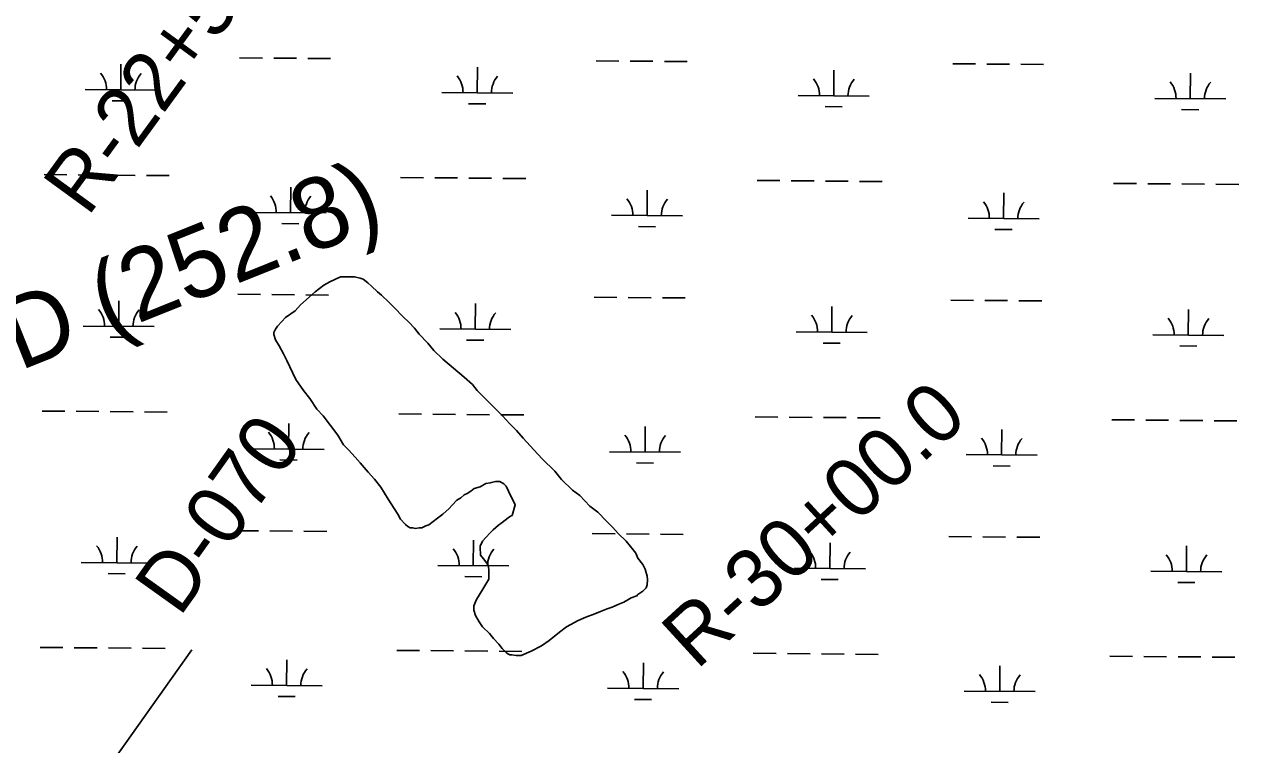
# Model space of a CAD drawing. Extents: x 3271442 to 3309282, y 752266 to 777610.
# Drawn here: x 3294405 to 3296115, y 767477 to 768491 of the extents above; entities that cross this region are included whole.
import ezdxf

# ---------------------------------------------------------------- set-up
doc = ezdxf.new("R2010")
doc.units = 0
for name, color, linetype in [('V-CHAN-NAID', 7, 'Continuous'), ('V-RIVR-RANG', 7, 'Continuous'), ('V-RIVR-RANG-IDEN', 7, 'Continuous'), ('V-SITE-VEGE', 7, 'Continuous'), ('V-WETL-SWMP', 7, 'Continuous')]:
    doc.layers.add(name, color=color, linetype=linetype)

msp = doc.modelspace()

# ---------------------------------------------------------------- linework, layer by layer
at = {"layer": 'V-RIVR-RANG'}
msp.add_line((3294641.4, 767611), (3293947, 766632.3), dxfattribs=at)
at = {"layer": 'V-SITE-VEGE'}
for points in [[(3294870.2, 768135.7), (3294850.4, 768135.7), (3294835.4, 768128.9), (3294827.3, 768124.2), (3294815, 768114.7), (3294794.5, 768096.3), (3294787, 768088.1), (3294773.4, 768078.6), (3294767.9, 768073.1), (3294761.8, 768066.3), (3294759, 768062.2), (3294757, 768057.5), (3294757, 768054.7), (3294759, 768047.2), (3294764.4, 768038.4), (3294770.6, 768027.4), (3294775.3, 768017.9), (3294787.6, 767991.3), (3294798.5, 767975.6), (3294807.3, 767964.7), (3294817.5, 767949.7), (3294826.4, 767940.1), (3294846.8, 767912.8), (3294855, 767899.2), (3294861.8, 767892.4), (3294871.3, 767882.1), (3294878.1, 767874), (3294889.7, 767861), (3294898.5, 767850.8), (3294907.4, 767839.8), (3294917.6, 767822.8), (3294931.2, 767801.6), (3294935.3, 767794.8), (3294942.1, 767787.3), (3294945.5, 767784.6), (3294948.9, 767782.5), (3294952.3, 767782.5), (3294956.4, 767781.8), (3294961.2, 767782.5), (3294965.3, 767782.5), (3294970.7, 767785.2), (3294974.8, 767786.6), (3294987.1, 767796.1), (3294994.6, 767801.6), (3295003.5, 767809.7), (3295007.6, 767814.5), (3295014.4, 767821.3), (3295019.8, 767824.7), (3295024.6, 767828.8), (3295028.7, 767830.9), (3295034.2, 767834.3), (3295038.9, 767837.7), (3295047.1, 767840.4), (3295055.3, 767845.1), (3295061.5, 767845.8), (3295069, 767847.9), (3295075.1, 767847.8), (3295080.5, 767844.4), (3295083.9, 767841), (3295087.3, 767834.2), (3295096.5, 767815), (3295092.1, 767800.1), (3295090, 767798.8), (3295086.6, 767796.7), (3295078.4, 767789.9), (3295073, 767786.5), (3295065.5, 767779.7), (3295061.4, 767775.6), (3295055.2, 767768.8), (3295050.5, 767764), (3295047, 767756.5), (3295047, 767752.4), (3295047.7, 767747), (3295047.7, 767744.3), (3295051.8, 767738.8), (3295056.6, 767732.7), (3295058.6, 767729.3), (3295059.3, 767723.8), (3295059.3, 767710.2), (3295055.2, 767703.4), (3295052.4, 767698.6), (3295045.6, 767687.7), (3295042.2, 767681.6), (3295038.1, 767672.7), (3295038.1, 767666.6), (3295040.8, 767659.1), (3295045.6, 767650.2), (3295050.3, 767643.4), (3295060.5, 767633.8), (3295066, 767627), (3295073.5, 767618.8), (3295078.2, 767612.7), (3295083.7, 767607.2), (3295086.4, 767605.2), (3295089.1, 767603.8), (3295091.9, 767603.8), (3295098, 767603.1), (3295104.8, 767603.1), (3295119.1, 767609.2), (3295133.5, 767616.7), (3295144.4, 767624.2)], [(3295144.4, 767624.2), (3295158.7, 767635.8), (3295168.9, 767643.2), (3295185.3, 767652.1), (3295196.2, 767656.9), (3295208.5, 767661.6), (3295216.7, 767665), (3295226.2, 767668.4), (3295233.1, 767671.1), (3295242.6, 767675.2), (3295249.4, 767677.9), (3295254.9, 767681.3), (3295259.6, 767684.1), (3295267.8, 767686.8), (3295269.2, 767688.8), (3295273.3, 767691.5), (3295276, 767693.6), (3295280.8, 767698.3), (3295282.2, 767702.4), (3295282.9, 767709.2), (3295282.2, 767714.7), (3295279.5, 767724.2), (3295276.1, 767731.1), (3295269.2, 767739.9), (3295266.5, 767746.8), (3295259, 767756.3), (3295252.9, 767763.8), (3295241.3, 767774.7), (3295233.8, 767782.9), (3295225, 767791.8), (3295212.7, 767804.8), (3295201.8, 767812.9), (3295187.5, 767828), (3295177.3, 767835.5), (3295161.7, 767850.5), (3295152.1, 767862.1), (3295134.4, 767879.8), (3295122.9, 767892.1), (3295107.9, 767908.5), (3295098.3, 767919.4), (3295088.8, 767929), (3295078.6, 767939.9), (3295064.3, 767954.9), (3295043.2, 767976), (3295036.4, 767984.2), (3295024.8, 767994.5), (3294994.8, 768019.7), (3294981.9, 768032), (3294973.7, 768042.2), (3294961.5, 768055.2), (3294954.7, 768063.4), (3294947.2, 768071.6), (3294938.3, 768079.8), (3294926.7, 768092), (3294919.3, 768099.5), (3294908.4, 768109.8), (3294902.9, 768114.6), (3294894.1, 768122.8), (3294889.3, 768127.5), (3294882.5, 768132.3), (3294878.4, 768133.7), (3294870.2, 768135.7)]]:
    msp.add_lwpolyline(points, dxfattribs=at)
at = {"layer": 'V-WETL-SWMP'}
for p, q in [((3294541.2, 768398.8), (3294541.5, 768434.8)), ((3294708.6, 768443.8), (3294740.6, 768443.6)), ((3294756.6, 768443.4), (3294788.6, 768443.2)), ((3294804.6, 768443), (3294836.6, 768442.8)), ((3295210.5, 768439.7), (3295242.5, 768439.4)), ((3295258.5, 768439.3), (3295290.5, 768439)), ((3295306.5, 768438.9), (3295338.5, 768438.6)), ((3295712.4, 768435.6), (3295744.4, 768435.3)), ((3295760.4, 768435.2), (3295792.4, 768434.9)), ((3295808.4, 768434.8), (3295840.4, 768434.5)), ((3295043.1, 768394.6), (3295043.4, 768430.6)), ((3295545, 768390.5), (3295545.3, 768426.5)), ((3296046.9, 768386.4), (3296047.2, 768422.4)), ((3294491.2, 768399.2), (3294591.2, 768398.4)), ((3294529.1, 768383.4), (3294553.1, 768383.3)), ((3294993.1, 768395.1), (3295093.1, 768394.2)), ((3295495, 768390.9), (3295595, 768390.1)), ((3295996.9, 768386.8), (3296096.9, 768386)), ((3295031, 768379.3), (3295055, 768379.1)), ((3295532.9, 768375.2), (3295556.9, 768375)), ((3296034.7, 768371), (3296058.7, 768370.8)), ((3294433.4, 768279.6), (3294465.4, 768279.3)), ((3294481.4, 768279.2), (3294513.4, 768278.9)), ((3294529.4, 768278.8), (3294561.4, 768278.5)), ((3294577.4, 768278.4), (3294609.4, 768278.1)), ((3294780.3, 768226), (3294780.6, 768262)), ((3294935.3, 768275.5), (3294967.3, 768275.2)), ((3294983.3, 768275.1), (3295015.3, 768274.8)), ((3295031.3, 768274.7), (3295063.3, 768274.4)), ((3295079.3, 768274.3), (3295111.3, 768274)), ((3295437.2, 768271.3), (3295469.2, 768271.1)), ((3295485.2, 768270.9), (3295517.2, 768270.7)), ((3295533.2, 768270.5), (3295565.2, 768270.3)), ((3295581.2, 768270.1), (3295613.1, 768269.9)), ((3295939, 768267.2), (3295971, 768266.9)), ((3295987, 768266.8), (3296019, 768266.5)), ((3296035, 768266.4), (3296067, 768266.1)), ((3296083, 768266), (3296115, 768265.7)), ((3295282.2, 768221.9), (3295282.4, 768257.9)), ((3295784, 768217.7), (3295784.3, 768253.7)), ((3294730.3, 768226.4), (3294830.3, 768225.6)), ((3294768.1, 768210.7), (3294792.1, 768210.5)), ((3295232.2, 768222.3), (3295332.1, 768221.4)), ((3295734, 768218.1), (3295834, 768217.3)), ((3295270, 768206.5), (3295294, 768206.3)), ((3295771.9, 768202.4), (3295795.9, 768202.2)), ((3294705.9, 768111.2), (3294737.9, 768110.9)), ((3294753.9, 768110.8), (3294785.9, 768110.5)), ((3294801.9, 768110.4), (3294833.9, 768110.1)), ((3294538.5, 768066.1), (3294538.8, 768102.1)), ((3295040.4, 768062), (3295040.7, 768098)), ((3295207.8, 768107), (3295239.8, 768106.8)), ((3295255.8, 768106.6), (3295287.8, 768106.4)), ((3295303.8, 768106.2), (3295335.8, 768106)), ((3295542.2, 768057.8), (3295542.5, 768093.8)), ((3295709.7, 768102.9), (3295741.7, 768102.6)), ((3295757.7, 768102.5), (3295789.7, 768102.2)), ((3295805.7, 768102.1), (3295837.7, 768101.8)), ((3296044.1, 768053.7), (3296044.4, 768089.7)), ((3294488.5, 768066.5), (3294588.5, 768065.7)), ((3294990.4, 768062.4), (3295090.4, 768061.6)), ((3295492.2, 768058.3), (3295592.2, 768057.4)), ((3294526.3, 768050.8), (3294550.3, 768050.6)), ((3295028.2, 768046.7), (3295052.2, 768046.5)), ((3295530.1, 768042.5), (3295554.1, 768042.3)), ((3295994.1, 768054.1), (3296094.1, 768053.3)), ((3296032, 768038.4), (3296056, 768038.2)), ((3294430.6, 767946.9), (3294462.6, 767946.7)), ((3294478.6, 767946.5), (3294510.6, 767946.3)), ((3294526.6, 767946.1), (3294558.6, 767945.9)), ((3294574.6, 767945.7), (3294606.6, 767945.5)), ((3294932.5, 767942.8), (3294964.5, 767942.5)), ((3294980.5, 767942.4), (3295012.5, 767942.1)), ((3295028.5, 767942), (3295060.5, 767941.7)), ((3295076.5, 767941.6), (3295108.5, 767941.3)), ((3295434.4, 767938.7), (3295466.4, 767938.4)), ((3295482.4, 767938.3), (3295514.4, 767938)), ((3295530.4, 767937.9), (3295562.4, 767937.6)), ((3295578.4, 767937.5), (3295610.4, 767937.2)), ((3294777.5, 767893.3), (3294777.8, 767929.3)), ((3295279.4, 767889.2), (3295279.7, 767925.2)), ((3295781.3, 767885.1), (3295781.6, 767921.1)), ((3295936.3, 767934.5), (3295968.3, 767934.3)), ((3295984.3, 767934.1), (3296016.3, 767933.9)), ((3296032.3, 767933.7), (3296064.3, 767933.5)), ((3296080.3, 767933.3), (3296112.3, 767933.1)), ((3294727.5, 767893.7), (3294827.5, 767892.9)), ((3295229.4, 767889.6), (3295329.4, 767888.8)), ((3295731.3, 767885.5), (3295831.3, 767884.6)), ((3294765.4, 767878), (3294789.4, 767877.8)), ((3295267.3, 767873.9), (3295291.3, 767873.7)), ((3295769.2, 767869.7), (3295793.2, 767869.5)), ((3294535.7, 767733.5), (3294536, 767769.5)), ((3294703.2, 767778.5), (3294735.2, 767778.2)), ((3294751.2, 767778.1), (3294783.2, 767777.8)), ((3294799.2, 767777.7), (3294831.2, 767777.5)), ((3295037.6, 767729.3), (3295037.9, 767765.3)), ((3295205.1, 767774.4), (3295237.1, 767774.1)), ((3295253.1, 767774), (3295285.1, 767773.7)), ((3295301.1, 767773.6), (3295333.1, 767773.3)), ((3295706.9, 767770.2), (3295738.9, 767770)), ((3295754.9, 767769.8), (3295786.9, 767769.6)), ((3295802.9, 767769.4), (3295834.9, 767769.2)), ((3295539.5, 767725.2), (3295539.8, 767761.2)), ((3296041.4, 767721.1), (3296041.7, 767757.1)), ((3294485.7, 767733.9), (3294585.7, 767733)), ((3294523.6, 767718.1), (3294547.6, 767717.9)), ((3294987.6, 767729.7), (3295087.6, 767728.9)), ((3295025.5, 767714), (3295049.5, 767713.8)), ((3295489.5, 767725.6), (3295589.5, 767724.8)), ((3295991.4, 767721.5), (3296091.4, 767720.6)), ((3295527.4, 767709.9), (3295551.4, 767709.7)), ((3296029.3, 767705.7), (3296053.3, 767705.5)), ((3294427.9, 767614.3), (3294459.9, 767614)), ((3294475.9, 767613.9), (3294507.9, 767613.6)), ((3294523.9, 767613.5), (3294555.9, 767613.2)), ((3294571.9, 767613.1), (3294603.9, 767612.8)), ((3294774.8, 767560.7), (3294775.1, 767596.7)), ((3294929.8, 767610.1), (3294961.8, 767609.9)), ((3294977.8, 767609.7), (3295009.8, 767609.5)), ((3295025.8, 767609.3), (3295057.8, 767609.1)), ((3295073.8, 767608.9), (3295105.8, 767608.7)), ((3295431.7, 767606), (3295463.7, 767605.7)), ((3295479.7, 767605.6), (3295511.7, 767605.3)), ((3295527.7, 767605.2), (3295559.7, 767604.9)), ((3295575.7, 767604.8), (3295607.7, 767604.5)), ((3295933.6, 767601.9), (3295965.6, 767601.6)), ((3295981.6, 767601.5), (3296013.6, 767601.2)), ((3296029.6, 767601.1), (3296061.6, 767600.8)), ((3296077.6, 767600.7), (3296109.6, 767600.4)), ((3295276.7, 767556.5), (3295277, 767592.5)), ((3295778.6, 767552.4), (3295778.9, 767588.4)), ((3294724.8, 767561.1), (3294824.8, 767560.3)), ((3294762.7, 767545.3), (3294786.7, 767545.1)), ((3295226.7, 767556.9), (3295326.7, 767556.1)), ((3295728.6, 767552.8), (3295828.6, 767552)), ((3295264.5, 767541.2), (3295288.5, 767541)), ((3295766.4, 767537.1), (3295790.4, 767536.9))]:
    msp.add_line(p, q, dxfattribs=at)
for centre, start, end in [((3294486, 768399.7), 358.7563, 40.2999), ((3294596.4, 768398.8), 138.7563, 180.2999), ((3294987.9, 768395.6), 358.7563, 40.2999), ((3295098.3, 768394.7), 138.7563, 180.2999), ((3295489.7, 768391.4), 358.7563, 40.2999), ((3295600.2, 768390.5), 138.7563, 180.2999), ((3295991.6, 768387.3), 358.7563, 40.2999), ((3296102.1, 768386.4), 138.7563, 180.2999), ((3294725, 768226.9), 358.7563, 40.2999), ((3294835.5, 768226), 138.7563, 180.2999), ((3295226.9, 768222.8), 358.7563, 40.2999), ((3295337.4, 768221.9), 138.7563, 180.2999), ((3295728.8, 768218.7), 358.7563, 40.2999), ((3295839.3, 768217.7), 138.7563, 180.2999), ((3294483.2, 768067), 358.7563, 40.2999), ((3294593.7, 768066.1), 138.7563, 180.2999), ((3294985.1, 768062.9), 358.7563, 40.2999), ((3295095.6, 768062), 138.7563, 180.2999), ((3295487, 768058.8), 358.7563, 40.2999), ((3295597.5, 768057.9), 138.7563, 180.2999), ((3295988.9, 768054.6), 358.7563, 40.2999), ((3296099.4, 768053.7), 138.7563, 180.2999), ((3294722.3, 767894.3), 358.7563, 40.2999), ((3294832.8, 767893.3), 138.7563, 180.2999), ((3295224.2, 767890.1), 358.7563, 40.2999), ((3295334.7, 767889.2), 138.7563, 180.2999), ((3295726.1, 767886), 358.7563, 40.2999), ((3295836.5, 767885.1), 138.7563, 180.2999), ((3294480.5, 767734.4), 358.7563, 40.2999), ((3294591, 767733.5), 138.7563, 180.2999), ((3294982.4, 767730.2), 358.7563, 40.2999), ((3295092.9, 767729.3), 138.7563, 180.2999), ((3295484.3, 767726.1), 358.7563, 40.2999), ((3295594.7, 767725.2), 138.7563, 180.2999), ((3295986.2, 767722), 358.7563, 40.2999), ((3296096.6, 767721.1), 138.7563, 180.2999), ((3294719.5, 767561.6), 358.7563, 40.2999), ((3294830, 767560.7), 138.7563, 180.2999), ((3295221.4, 767557.5), 358.7563, 40.2999), ((3295331.9, 767556.6), 138.7563, 180.2999), ((3295723.3, 767553.3), 358.7563, 40.2999), ((3295833.8, 767552.4), 138.7563, 180.2999)]:
    msp.add_arc(centre, 35.2, start, end, dxfattribs=at)

# ---------------------------------------------------------------- texts
at = {"layer": 'V-CHAN-NAID'}
msp.add_text('PROFIT ISLAND (252.8)', height=100, rotation=21.8236, dxfattribs=at).set_placement((3293550.5, 767663.4))
at = {"layer": 'V-RIVR-RANG-IDEN'}
for s, rotation, p in [('R-22+50.0', 53.9002, (3294494.9, 768218.9)), ('R-30+00.0', 42.5096, (3295352, 767581.6)), ('D-070', 54.4973, (3294624.1, 767655.6))]:
    msp.add_text(s, height=83, rotation=rotation, dxfattribs=at).set_placement(p)

doc.saveas('drawing.dxf')
